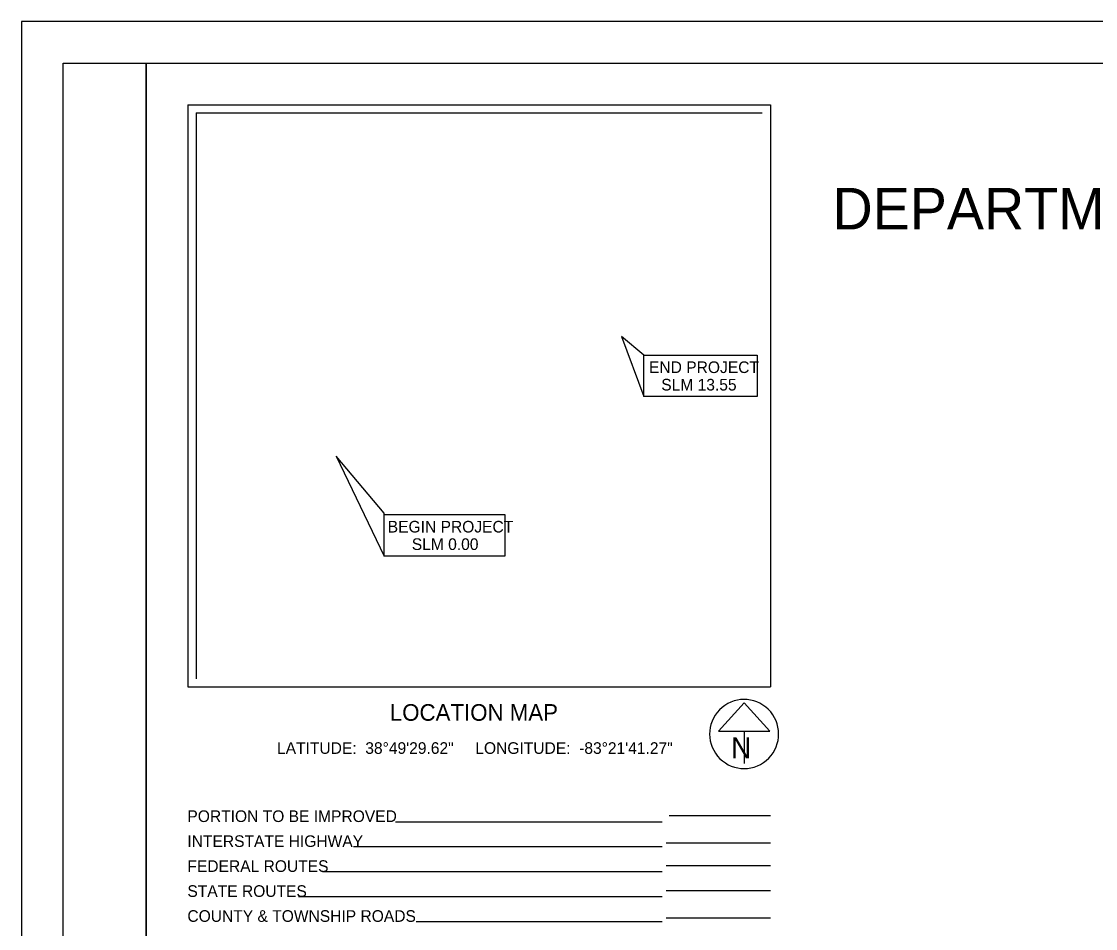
# Model space of a CAD drawing. Extents: x 0 to 34, y 0 to 22.
# Drawn here: x 0 to 12.91, y 11.1 to 22 of the extents above; entities that cross this region are included whole.
import ezdxf

# ---------------------------------------------------------------- set-up
doc = ezdxf.new("R2010")
doc.units = 0
for name, color, linetype in [('Default', 7, 'Continuous'), ('SH_Border', 7, 'Continuous'), ('SH_Cut_Line', 7, 'Continuous'), ('SH_Data', 7, 'Continuous'), ('SH_Text', 7, 'Continuous')]:
    doc.layers.add(name, color=color, linetype=linetype)

msp = doc.modelspace()

# ---------------------------------------------------------------- linework, layer by layer
at = {"layer": 'Default'}
for points in [[(7.48, 17.99), (7.21, 18.212), (7.48, 17.493)], [(7.48, 17.99), (8.84, 17.99), (8.84, 17.493), (7.48, 17.493)], [(4.357, 16.088), (3.78, 16.776), (4.357, 15.574)], [(4.357, 16.072), (5.81, 16.072), (5.81, 15.574), (4.357, 15.574)]]:
    msp.add_lwpolyline(points, close=True, dxfattribs=at)
at = {"layer": 'SH_Border'}
for points in [[(0.5, 21.5), (1.5, 21.5), (1.5, 0.5), (0.5, 0.5)], [(1.5, 21.5), (33.5, 21.5), (33.5, 0.5), (1.5, 0.5)]]:
    msp.add_lwpolyline(points, close=True, dxfattribs=at)
at = {"layer": 'SH_Cut_Line'}
msp.add_lwpolyline([(0, 0), (34, 0), (34, 22), (0, 22)], close=True, dxfattribs=at)
at = {"layer": 'SH_Data'}
for p, q in [((2, 21), (9, 21)), ((2, 21), (2, 14)), ((9, 21), (9, 14)), ((2.1, 20.9), (2.1, 14.1)), ((2.1, 20.9), (8.9, 20.9)), ((2.1, 14.1), (2.1, 14.1)), ((2, 14), (9, 14)), ((8.685, 13.809), (8.377, 13.468)), ((8.992, 13.468), (8.685, 13.809)), ((8.377, 13.468), (8.992, 13.468)), ((8.685, 13.468), (8.685, 13.081)), ((8.685, 13.435), (8.685, 13.435)), ((8.685, 13.435), (8.685, 13.435)), ((7.783, 12.455), (9, 12.455)), ((7.7, 12.377), (4.494, 12.377)), ((7.7, 12.077), (3.99, 12.077)), ((9, 12.121), (7.75, 12.121)), ((7.7, 11.777), (3.619, 11.777)), ((9, 11.849), (7.75, 11.849)), ((9, 11.549), (7.75, 11.549)), ((7.7, 11.477), (3.329, 11.477)), ((7.7, 11.177), (4.745, 11.177)), ((9, 11.222), (7.75, 11.222))]:
    msp.add_line(p, q, dxfattribs=at)
msp.add_arc((8.685, 13.435), 0.415, 129.7798, 129.7633, dxfattribs=at)

# ---------------------------------------------------------------- texts
at = {"layer": 'Default'}
for s, p in [('END PROJECT', (7.542, 17.774)), ('SLM 13.55', (7.689, 17.564)), ('BEGIN PROJECT', (4.402, 15.857)), ('SLM 0.00', (4.691, 15.647))]:
    msp.add_text(s, height=0.14, dxfattribs=at).set_placement(p)
at = {"layer": 'SH_Data'}
msp.add_text('N', height=0.25, dxfattribs=at).set_placement((8.529, 13.144))
at = {"layer": 'SH_Text'}
for s, height, p in [('DEPARTMENT OF TRANSPORTATION', 0.5, (9.747, 19.5)), ('LOCATION MAP', 0.2, (4.427, 13.594)), ('LATITUDE:  38°49\'29.62"     LONGITUDE:  -83°21\'41.27"', 0.14, (3.071, 13.196)), ('PORTION TO BE IMPROVED', 0.14, (1.994, 12.377)), ('INTERSTATE HIGHWAY', 0.14, (1.994, 12.077)), ('FEDERAL ROUTES', 0.14, (1.994, 11.777)), ('STATE ROUTES', 0.14, (1.994, 11.477)), ('COUNTY & TOWNSHIP ROADS', 0.14, (1.994, 11.177))]:
    msp.add_text(s, height=height, dxfattribs=at).set_placement(p)

doc.saveas('drawing.dxf')
